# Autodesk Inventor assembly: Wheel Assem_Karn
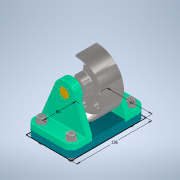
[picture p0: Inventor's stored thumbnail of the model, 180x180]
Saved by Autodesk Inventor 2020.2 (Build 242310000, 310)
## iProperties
Created: 2019-10
Part Number: Wheel Assem_Karn
Document SubType Name: Assembly
Designer: Synergysoft Dell02
Author: Synergysoft Dell02
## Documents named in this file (9)
- C:\Users\Synergysoft Dell02\Desktop\INV-01 Intro to Modeling_2020\Wheel Assem_Karn.iam
- C:\Users\Synergysoft Dell02\Desktop\INV-01 Intro to Modeling_2020\Wheel Assem Final V1\Plate V1.ipt
- C:\Users\Synergysoft Dell02\Desktop\INV-01 Intro to Modeling_2020\Wheel Assem Final V1\Shaft V1.ipt
- C:\Users\Synergysoft Dell02\Desktop\INV-01 Intro to Modeling_2020\Wheel Assem Final V1\Support Wheel V1.ipt
- C:\Users\Synergysoft Dell02\Desktop\INV-01 Intro to Modeling_2020\Wheel Assem Final V1\Wheel V1.ipt
- C:\Users\Synergysoft Dell02\Desktop\INV-01 Intro to Modeling_2020\Wheel Assem_Karn\Design Accelerator\Bolted Connection1.iam
- C:\Users\Synergysoft Dell02\Desktop\INV-01 Intro to Modeling_2020\Wheel Assem_Karn\Design Accelerator\Bolted Connection2.iam
- C:\Users\Synergysoft Dell02\Desktop\INV-01 Intro to Modeling_2020\Wheel Assem_Karn\Design Accelerator\Bolted Connection3.iam
- C:\Users\Synergysoft Dell02\Desktop\INV-01 Intro to Modeling_2020\Wheel Assem_Karn\Design Accelerator\Bolted Connection4.iam
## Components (9 placed, 5 different names)
1. Plate V1:1 — Insert:1, Mate:1, Insert:2, Insert:3
2. Shaft V1:1 — Mate:2, Flush:1, Mate:3, Flush:2
3. Support Wheel V1:1 — Insert:1, Mate:1, Mate:2, Flush:1, Mate:8, Mate:9, Mate:10, Mate:11
4. Wheel V1:1 — Mate:3, Flush:2
5. Support Wheel V1:2 — Insert:2, Insert:3, Mate:4, Mate:5, Mate:6, Mate:7
6. Bolted Connection:1 [sub-assembly] — Mate:4, Mate:5
7. Bolted Connection:2 [sub-assembly] — Mate:6, Mate:7
8. Bolted Connection:3 [sub-assembly] — Mate:8, Mate:9
9. Bolted Connection:4 [sub-assembly] — Mate:10, Mate:11
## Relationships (16: Mate 11, Insert 3, Flush 2)
- Insert:1: Plate V1:1 ↔ Support Wheel V1:1
- Mate:1: Plate V1:1 ↔ Support Wheel V1:1
- Insert:2: Plate V1:1 ↔ Support Wheel V1:2
- Insert:3: Plate V1:1 ↔ Support Wheel V1:2
- Mate:2: Shaft V1:1 ↔ Support Wheel V1:1
- Flush:1: Shaft V1:1 ↔ Support Wheel V1:1
- Mate:3: Shaft V1:1 ↔ Wheel V1:1
- Flush:2: Shaft V1:1 ↔ Wheel V1:1
- Mate:4: Support Wheel V1:2 ↔ Bolted Connection:1
- Mate:5: Support Wheel V1:2 ↔ Bolted Connection:1
- Mate:6: Support Wheel V1:2 ↔ Bolted Connection:2
- Mate:7: Support Wheel V1:2 ↔ Bolted Connection:2
- Mate:8: Support Wheel V1:1 ↔ Bolted Connection:3
- Mate:9: Support Wheel V1:1 ↔ Bolted Connection:3
- Mate:10: Support Wheel V1:1 ↔ Bolted Connection:4
- Mate:11: Support Wheel V1:1 ↔ Bolted Connection:4
